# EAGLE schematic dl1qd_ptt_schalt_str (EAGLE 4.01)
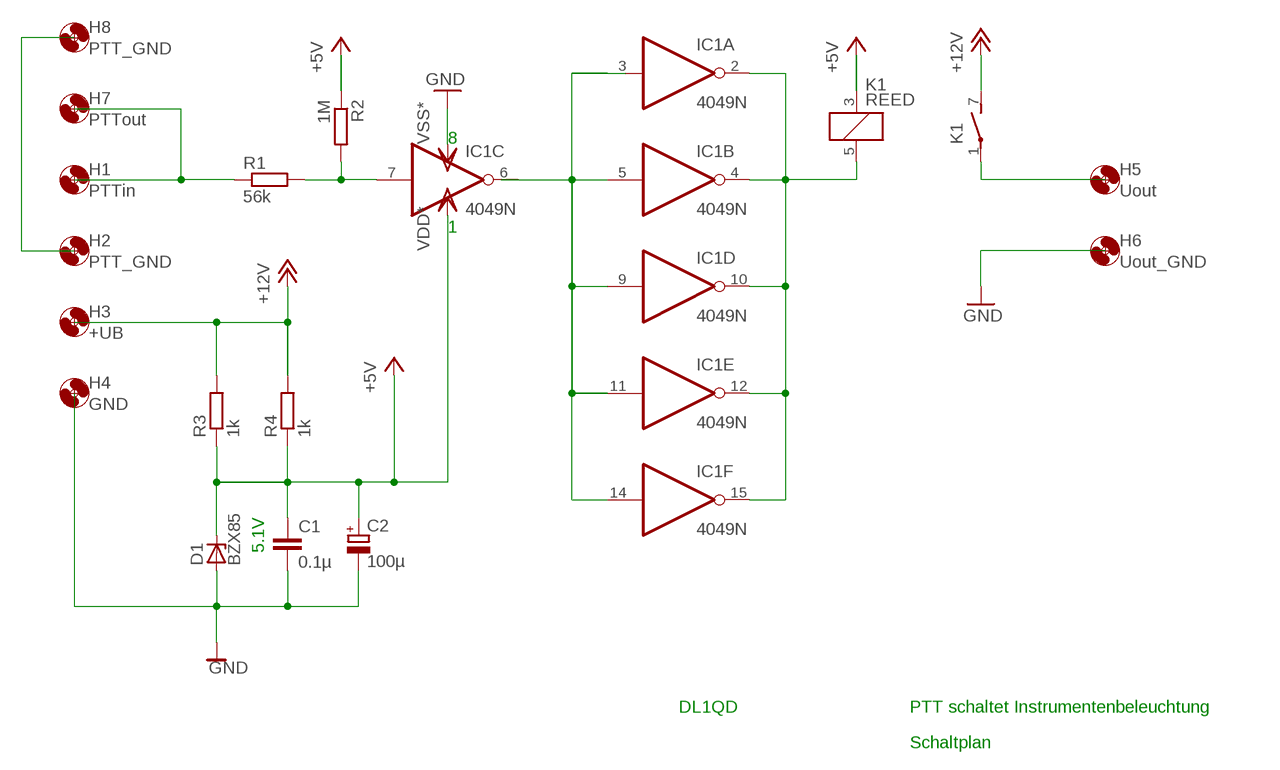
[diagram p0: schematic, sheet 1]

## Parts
C1  0.1µ  C-EU050-025X075  [C050-025X075]
C2  100µ  CPOL-EUE5-6  [E5-6]
D1  BZX85  [DO41Z10]
H1  PTTin  MOUNT-HOLE2.8  [2,8]
H2  PTT_GND  MOUNT-HOLE2.8  [2,8]
H3  +UB  MOUNT-HOLE2.8  [2,8]
H4  GND  MOUNT-HOLE2.8  [2,8]
H5  Uout  MOUNT-HOLE2.8  [2,8]
H6  Uout_GND  MOUNT-HOLE2.8  [2,8]
H7  PTTout  MOUNT-HOLE2.8  [2,8]
H8  PTT_GND  MOUNT-HOLE2.8  [2,8]
IC1  4049N  [DIL16]
K1  REED  [REED]
R1  56k  R-EU_0207/10  [0207/10]
R2  1M  R-EU_0207/10  [0207/10]
R3  1k  R-EU_0207/10  [0207/10]
R4  1k  R-EU_0207/10  [0207/10]

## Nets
0V: C1.1 C2.- D1.A ; supply symbol labelled GND
+5V: C1.2 C2.+ D1.K(C) K1.3(1:+) R2.1 R3.1 R4.1 ; supply symbol labelled VDD*
+12V: K1.7(2:S) R3.2 R4.2
N$1: R1.1
N$2: IC1.7(C:I) R1.2 R2.2
N$3: K1.1(2:P)
N$4: IC1.3(A:I) IC1.5(B:I) IC1.6(C:O) IC1.9(D:I) IC1.11(E:I) IC1.14(F:I)
N$7: IC1.2(A:O) IC1.4(B:O) IC1.10(D:O) IC1.12(E:O) IC1.15(F:O) K1.5(1:-)

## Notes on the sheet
- 8
- 1
- 5.1V
- DL1QD | PTT schaltet Instrumentenbeleuchtung
- Schaltplan

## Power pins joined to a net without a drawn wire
VDD: IC1.1(P:VDD)
VSS: IC1.8(P:VSS)

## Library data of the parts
C1 = rcl:C-EU: CAPACITOR, European symbol
C2 = rcl:CPOL-EU: POLARIZED CAPACITOR, European symbol
D1 = diode:BZX85: Z DIODE
H1-H8 = holes:MOUNT-HOLE: MOUNTING HOLE with drill center marker
IC1 = 40xx:4049: Hex inverting BUFFER
K1 = relay:REED: RELAY reed, 1 x norm. open with polarity, grid 5.08
R1-R4 = rcl:R-EU_: RESISTOR, European symbol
